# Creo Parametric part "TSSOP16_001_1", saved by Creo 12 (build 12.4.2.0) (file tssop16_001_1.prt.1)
Units: Custom; MM, KILOGRAM, SECS

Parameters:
  PTC_WM_ITERATION = "0"
  PTC_WM_VERSION = "-.0"
  PTC_WM_LIFECYCLE_STATE = "In Work"
  PTC_WM_LIFECYCLE = "MO_CADDocument"
  PTC_WM_CREATED_BY = "Maximilian Roepper (Z0017RMS: MO)"
  PTC_WM_CREATED_ON = "18-Sep-26 11:36:42 AM"
  PTC_WM_MODIFIED_BY = "Maximilian Roepper (Z0017RMS: MO)"
  PTC_WM_MODIFIED_ON = "18-Sep-26 11:36:46 AM"
  PDMLINKNUMBER = "PDM000071455018"
  PTC_WM_NAME = "tssop16_001_1.prt"
  PTC_WM_NUMBER = "PDM000071455018"

Other parameters: WEIGHT, WEIGHT_FACTOR, WEIGHT_ADD, _MASS_TEMP, _DIFF_TEMP, MC_ERRORS, SUPPLIER

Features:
  1. coordinate system
  2. datum plane "PRT_YZ"
  3. datum plane "PRT_XY"
  4. datum plane "PRT_XZ"
  5. coordinate system
  6. datum axis
  7. datum axis
  8. datum axis
  9. coordinate system
  10. imported feature
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
Other named items: PRT, SIEMENS_MO, DRW_VIEW_ORG, PRT_X, PRT_Y, PRT_Z, CS0, ROUGH_GROB

Layers: 00_STD_CSYS-KSYS, 01_STD_PLANES-EBENEN, 02_STD_AXES-ACHSEN, 03_STD_CSYS-KSYS, 24_IMPORT_FEAT-IMPORT_KE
